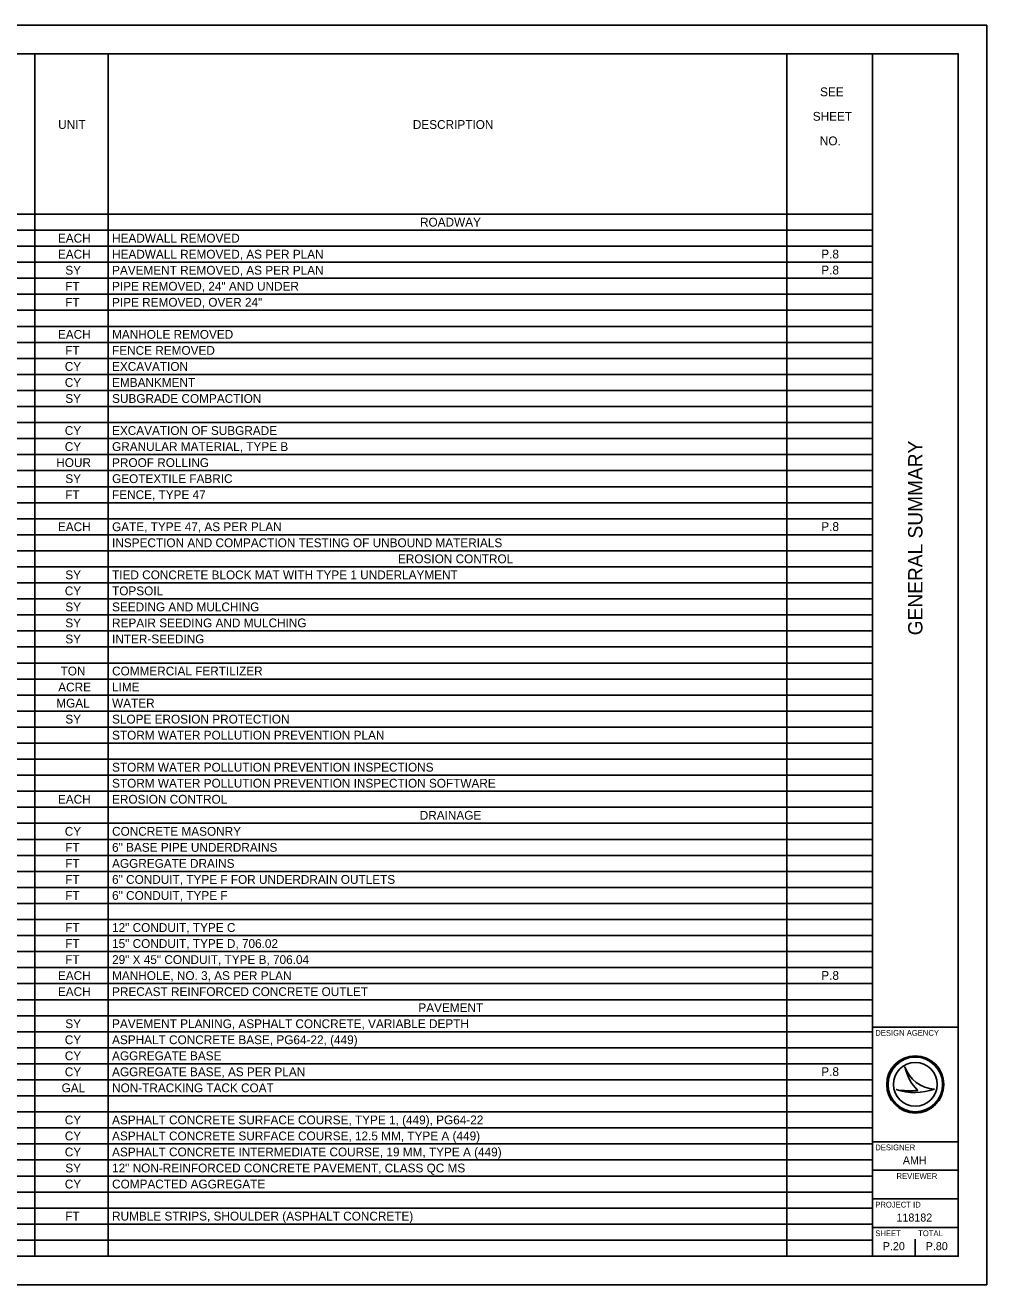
# Model space of a CAD drawing. Extents: x 0 to 34, y 0 to 22.
# Drawn here: x 17.19 to 34, y 0 to 22 of the extents above; entities that cross this region are included whole.
import ezdxf

# ---------------------------------------------------------------- set-up
doc = ezdxf.new("R2010")
doc.units = 0
for name, color, linetype in [('SH_Border', 7, 'Continuous'), ('SH_Cut_Line', 7, 'Continuous'), ('SH_Data', 7, 'Continuous'), ('SH_Text', 7, 'Continuous')]:
    doc.layers.add(name, color=color, linetype=linetype)

msp = doc.modelspace()

# ---------------------------------------------------------------- linework, layer by layer
at = {"layer": 'SH_Border'}
for p, q in [((32, 0.5), (32, 21.5)), ((32, 4.5), (33.5, 4.5)), ((32, 2.5), (33.5, 2.5)), ((32, 2), (33.5, 2)), ((32, 1.5), (33.5, 1.5)), ((32, 1), (33.5, 1))]:
    msp.add_line(p, q, dxfattribs=at)
msp.add_lwpolyline([(1.5, 21.5), (33.5, 21.5), (33.5, 0.5), (1.5, 0.5)], close=True, dxfattribs=at)
at = {"layer": 'SH_Cut_Line'}
msp.add_lwpolyline([(0, 0), (34, 0), (34, 22), (0, 22)], close=True, dxfattribs=at)
at = {"layer": 'SH_Data'}
for p, q in [((32.567, 3.81), (32.567, 3.81)), ((32.417, 3.41), (32.417, 3.41)), ((32.75, 3.5), (32.75, 3.5)), ((33.087, 3.419), (33.087, 3.419)), ((32.375, 0.675), (32.375, 0.675)), ((32.75, 0.5), (32.75, 0.8))]:
    msp.add_line(p, q, dxfattribs=at)
for radius in [0.5, 0.477, 0.477, 0.382]:
    msp.add_circle((32.75, 3.5), radius, dxfattribs=at)
for centre, radius, start, end in [((33.116, 3.998), 0.58, 198.9257, 198.9319), ((33.347, 3.97), 0.796, 191.6379, 191.6421), ((33.116, 3.998), 0.58, 198.9319, 267.1657), ((33.347, 3.97), 0.796, 191.6421, 226.0947), ((32.739, 4.37), 1.013, 251.4576, 290.0832), ((32.648, 4.654), 1.266, 259.4964, 259.4995), ((32.739, 4.37), 1.013, 251.4527, 251.4576), ((32.648, 4.654), 1.266, 259.4995, 276.6672)]:
    msp.add_arc(centre, radius, start, end, dxfattribs=at)
at = {"layer": 'SH_Text'}
for p, q in [((1.5, 21.5), (31.987, 21.5)), ((17.361, 21.5), (17.361, 0.5)), ((18.646, 21.5), (18.646, 0.5)), ((30.505, 21.5), (30.505, 0.5)), ((1.5, 18.7), (31.987, 18.7)), ((1.5, 18.42), (31.987, 18.42)), ((1.5, 18.14), (31.987, 18.14)), ((1.5, 17.86), (31.987, 17.86)), ((1.5, 17.58), (31.987, 17.58)), ((1.5, 17.3), (31.987, 17.3)), ((1.5, 17.02), (31.987, 17.02)), ((1.5, 16.74), (31.987, 16.74)), ((1.5, 16.46), (31.987, 16.46)), ((1.5, 16.18), (31.987, 16.18)), ((1.5, 15.9), (31.987, 15.9)), ((1.5, 15.62), (31.987, 15.62)), ((1.5, 15.34), (31.987, 15.34)), ((1.5, 15.06), (31.987, 15.06)), ((1.5, 14.78), (31.987, 14.78)), ((1.5, 14.5), (31.987, 14.5)), ((1.5, 14.22), (31.987, 14.22)), ((1.5, 13.94), (31.987, 13.94)), ((1.5, 13.66), (31.987, 13.66)), ((1.5, 13.38), (31.987, 13.38)), ((1.5, 13.1), (31.987, 13.1)), ((1.5, 12.82), (31.987, 12.82)), ((1.5, 12.54), (31.987, 12.54)), ((1.5, 12.26), (31.987, 12.26)), ((1.5, 11.98), (31.987, 11.98)), ((1.5, 11.7), (31.987, 11.7)), ((1.5, 11.42), (31.987, 11.42)), ((1.5, 11.14), (31.987, 11.14)), ((1.5, 10.86), (31.987, 10.86)), ((1.5, 10.58), (31.987, 10.58)), ((1.5, 10.3), (31.987, 10.3)), ((1.5, 10.02), (31.987, 10.02)), ((1.5, 9.74), (31.987, 9.74)), ((1.5, 9.46), (31.987, 9.46)), ((1.5, 9.18), (31.987, 9.18)), ((1.5, 8.9), (31.987, 8.9)), ((1.5, 8.62), (31.987, 8.62)), ((1.5, 8.34), (31.987, 8.34)), ((1.5, 8.06), (31.987, 8.06)), ((1.5, 7.78), (31.987, 7.78)), ((1.5, 7.5), (31.987, 7.5)), ((1.5, 7.22), (31.987, 7.22)), ((1.5, 6.94), (31.987, 6.94)), ((1.5, 6.66), (31.987, 6.66)), ((1.5, 6.38), (31.987, 6.38)), ((1.5, 6.1), (31.987, 6.1)), ((1.5, 5.82), (31.987, 5.82)), ((1.5, 5.54), (31.987, 5.54)), ((1.5, 5.26), (31.987, 5.26)), ((1.5, 4.98), (31.987, 4.98)), ((1.5, 4.7), (31.987, 4.7)), ((1.5, 4.42), (31.987, 4.42)), ((1.5, 4.14), (31.987, 4.14)), ((1.5, 3.86), (31.987, 3.86)), ((1.5, 3.58), (31.987, 3.58)), ((1.5, 3.3), (31.987, 3.3)), ((1.5, 3.02), (31.987, 3.02)), ((1.5, 2.74), (31.987, 2.74)), ((1.5, 2.46), (31.987, 2.46)), ((1.5, 2.18), (31.987, 2.18)), ((1.5, 1.9), (31.987, 1.9)), ((1.5, 1.62), (31.987, 1.62)), ((1.5, 1.34), (31.987, 1.34)), ((1.5, 1.06), (31.987, 1.06)), ((1.5, 0.78), (31.987, 0.78))]:
    msp.add_line(p, q, dxfattribs=at)

# ---------------------------------------------------------------- texts
at = {"layer": 'SH_Data'}
msp.add_text('GENERAL SUMMARY', height=0.25, rotation=90, dxfattribs=at).set_placement((32.875, 11.344))
for s, height, p in [('DESIGN AGENCY', 0.1, (32.05, 4.35)), ('DESIGNER', 0.1, (32.05, 2.35)), ('AMH', 0.14, (32.532, 2.105)), ('REVIEWER', 0.1, (32.422, 1.85)), ('PROJECT ID', 0.1, (32.05, 1.35)), ('118182', 0.14, (32.421, 1.105)), ('SHEET', 0.1, (32.05, 0.85)), ('TOTAL', 0.1, (32.8, 0.85)), ('P.20', 0.14, (32.182, 0.605)), ('P.80', 0.14, (32.932, 0.605))]:
    msp.add_text(s, height=height, dxfattribs=at).set_placement(p)
at = {"layer": 'SH_Text'}
for s, p in [('SEE', (31.086, 20.759)), ('SHEET', (30.958, 20.331)), ('UNIT', (17.77, 20.188)), ('DESCRIPTION', (23.969, 20.188)), ('NO.', (31.082, 19.902)), ('ROADWAY', (24.094, 18.483)), ('EACH', (17.766, 18.203)), ('HEADWALL REMOVED', (18.712, 18.203)), ('EACH', (17.766, 17.923)), ('HEADWALL REMOVED, AS PER PLAN', (18.712, 17.923)), ('P.8', (31.107, 17.926)), ('SY', (17.895, 17.643)), ('PAVEMENT REMOVED, AS PER PLAN', (18.712, 17.643)), ('P.8', (31.107, 17.646)), ('FT', (17.893, 17.363)), ('PIPE REMOVED, 24" AND UNDER', (18.712, 17.363)), ('FT', (17.893, 17.083)), ('PIPE REMOVED, OVER 24"', (18.712, 17.083)), ('EACH', (17.766, 16.523)), ('MANHOLE REMOVED', (18.712, 16.523)), ('FT', (17.893, 16.243)), ('FENCE REMOVED', (18.712, 16.243)), ('CY', (17.886, 15.963)), ('EXCAVATION', (18.712, 15.963)), ('CY', (17.886, 15.683)), ('EMBANKMENT', (18.712, 15.683)), ('SY', (17.895, 15.403)), ('SUBGRADE COMPACTION', (18.712, 15.403)), ('CY', (17.886, 14.843)), ('EXCAVATION OF SUBGRADE', (18.712, 14.843)), ('CY', (17.886, 14.563)), ('GRANULAR MATERIAL, TYPE B', (18.712, 14.563)), ('HOUR', (17.737, 14.283)), ('PROOF ROLLING', (18.712, 14.283)), ('SY', (17.895, 14.003)), ('GEOTEXTILE FABRIC', (18.712, 14.003)), ('FT', (17.893, 13.723)), ('FENCE, TYPE 47', (18.712, 13.723)), ('EACH', (17.766, 13.163)), ('GATE, TYPE 47, AS PER PLAN', (18.712, 13.163)), ('P.8', (31.107, 13.166)), ('INSPECTION AND COMPACTION TESTING OF UNBOUND MATERIALS', (18.712, 12.883)), ('EROSION CONTROL', (23.709, 12.603)), ('SY', (17.895, 12.323)), ('TIED CONCRETE BLOCK MAT WITH TYPE 1 UNDERLAYMENT', (18.712, 12.323)), ('CY', (17.886, 12.043)), ('TOPSOIL', (18.712, 12.043)), ('SY', (17.895, 11.763)), ('SEEDING AND MULCHING', (18.712, 11.763)), ('SY', (17.895, 11.483)), ('REPAIR SEEDING AND MULCHING', (18.712, 11.483)), ('SY', (17.895, 11.203)), ('INTER-SEEDING', (18.712, 11.203)), ('TON', (17.812, 10.643)), ('COMMERCIAL FERTILIZER', (18.712, 10.643)), ('ACRE', (17.771, 10.363)), ('LIME', (18.712, 10.363)), ('MGAL', (17.737, 10.083)), ('WATER', (18.712, 10.083)), ('SY', (17.895, 9.803)), ('SLOPE EROSION PROTECTION', (18.712, 9.803)), ('STORM WATER POLLUTION PREVENTION PLAN', (18.712, 9.523)), ('STORM WATER POLLUTION PREVENTION INSPECTIONS', (18.712, 8.963)), ('STORM WATER POLLUTION PREVENTION INSPECTION SOFTWARE', (18.712, 8.683)), ('EACH', (17.766, 8.403)), ('EROSION CONTROL', (18.712, 8.403)), ('DRAINAGE', (24.089, 8.123)), ('CY', (17.886, 7.843)), ('CONCRETE MASONRY', (18.712, 7.843)), ('FT', (17.893, 7.563)), ('6" BASE PIPE UNDERDRAINS', (18.712, 7.563)), ('FT', (17.893, 7.283)), ('AGGREGATE DRAINS', (18.712, 7.283)), ('FT', (17.893, 7.003)), ('6" CONDUIT, TYPE F FOR UNDERDRAIN OUTLETS', (18.712, 7.003)), ('FT', (17.893, 6.723)), ('6" CONDUIT, TYPE F', (18.712, 6.723)), ('FT', (17.893, 6.163)), ('12" CONDUIT, TYPE C', (18.712, 6.163)), ('FT', (17.893, 5.883)), ('15" CONDUIT, TYPE D, 706.02', (18.712, 5.883)), ('FT', (17.893, 5.603)), ('29" X 45" CONDUIT, TYPE B, 706.04', (18.712, 5.603)), ('EACH', (17.766, 5.323)), ('MANHOLE, NO. 3, AS PER PLAN', (18.712, 5.323)), ('P.8', (31.107, 5.326)), ('EACH', (17.766, 5.043)), ('PRECAST REINFORCED CONCRETE OUTLET', (18.712, 5.043)), ('PAVEMENT', (24.065, 4.763)), ('SY', (17.895, 4.483)), ('PAVEMENT PLANING, ASPHALT CONCRETE, VARIABLE DEPTH', (18.712, 4.483)), ('CY', (17.886, 4.203)), ('ASPHALT CONCRETE BASE, PG64-22, (449)', (18.712, 4.203)), ('CY', (17.886, 3.923)), ('AGGREGATE BASE', (18.712, 3.923)), ('CY', (17.886, 3.643)), ('AGGREGATE BASE, AS PER PLAN', (18.712, 3.643)), ('P.8', (31.107, 3.646)), ('GAL', (17.83, 3.363)), ('NON-TRACKING TACK COAT', (18.712, 3.363)), ('CY', (17.886, 2.803)), ('ASPHALT CONCRETE SURFACE COURSE, TYPE 1, (449), PG64-22', (18.712, 2.803)), ('CY', (17.886, 2.523)), ('ASPHALT CONCRETE SURFACE COURSE, 12.5 MM, TYPE A (449)', (18.712, 2.523)), ('CY', (17.886, 2.243)), ('ASPHALT CONCRETE INTERMEDIATE COURSE, 19 MM, TYPE A (449)', (18.712, 2.243)), ('SY', (17.895, 1.963)), ('12" NON-REINFORCED CONCRETE PAVEMENT, CLASS QC MS', (18.712, 1.963)), ('CY', (17.886, 1.683)), ('COMPACTED AGGREGATE', (18.712, 1.683)), ('FT', (17.893, 1.123)), ('RUMBLE STRIPS, SHOULDER (ASPHALT CONCRETE)', (18.712, 1.123))]:
    msp.add_text(s, height=0.154, dxfattribs=at).set_placement(p)

doc.saveas('drawing.dxf')
